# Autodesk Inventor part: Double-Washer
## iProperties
Company: Autodesk, Inc.
Shininess: 64.0
Length Units: 11269
Angle Units: 11279
Time Units: 11290
Mass Units: 11283
Length Display Precision: 3
Angle Display Precision: 2
Compacted: True
Part Number: Double-Washer
Document SubType Name: Modeling
Created: 2003-12
Catalog Web Link: www.autodesk.com
Vendor: Autodesk, Inc.
Designer: Administrator
Manufacturer: Standard
Standards Organization: Custom
Density: 1 g/cm^3
Density: 0.0
Volumn: 0.0
Area: 0.0
PropertySet Name: Model Information
Control State: 0
Master: False
Checked Out: False
Author: Administrator
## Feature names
1. Revolution1
